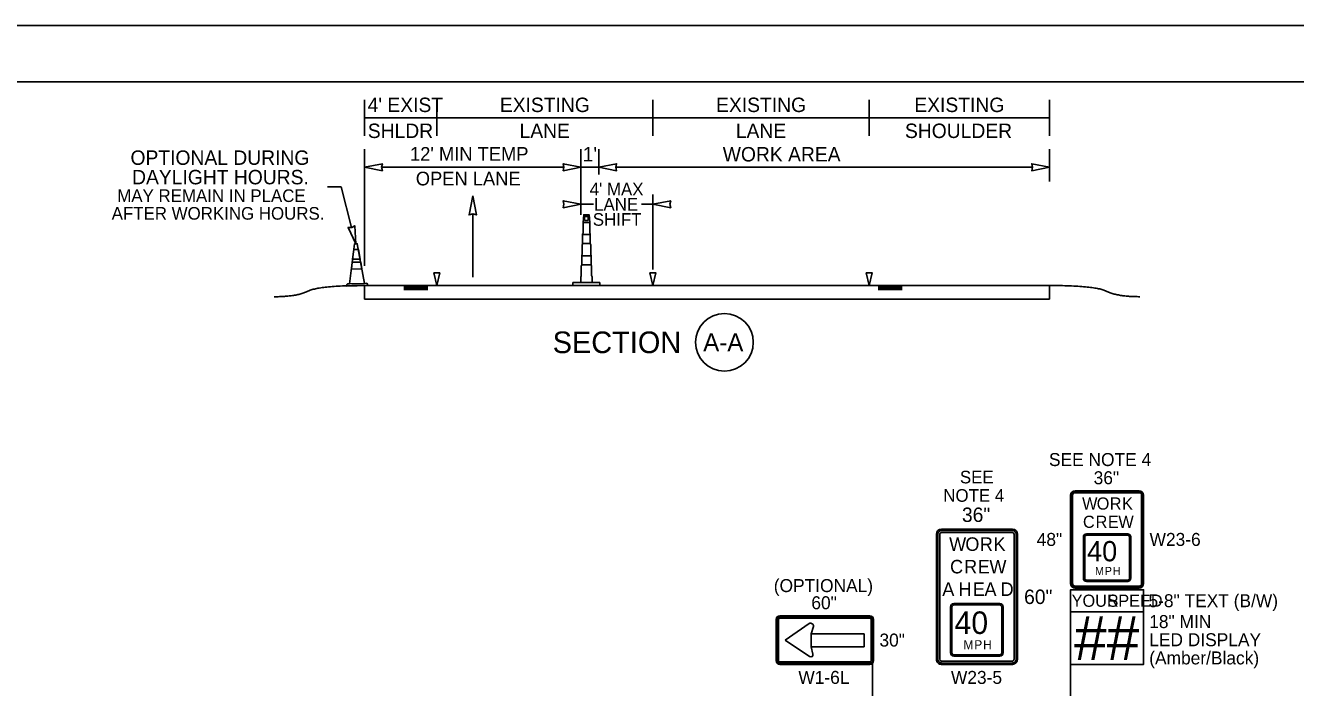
# Model space of a CAD drawing. Extents: x 99999 to 100116, y 99995 to 100013.
# Drawn here: x 100024.18 to 100031.22, y 100007.02 to 100010.69 of the extents above; entities that cross this region are included whole.
import ezdxf

# ---------------------------------------------------------------- set-up
doc = ezdxf.new("R2010")
doc.units = 0
for name, color, linetype in [('SH_GI_PlotLimits', 7, 'Continuous'), ('SH_GI_SheetBorder', 7, 'Continuous'), ('SH_TI_WZSectionCut', 7, 'Continuous'), ('TR_SN_ConstructionSigns', 7, 'Continuous'), ('TR_WZ_ArrowLeftStrRightTurn', 7, 'Continuous'), ('TR_WZ_TallChanDeviceElev', 7, 'Continuous'), ('TR_WZ_TrafficConeElev', 7, 'Continuous'), ('TR_WZ_WorkZoneDetails', 7, 'Continuous'), ('TR_WZ_WorkZoneTextCurrent', 7, 'Continuous')]:
    doc.layers.add(name, color=color, linetype=linetype)

msp = doc.modelspace()

# ---------------------------------------------------------------- linework, layer by layer
at = {"layer": 'SH_GI_PlotLimits'}
msp.add_lwpolyline([(100019.0625, 99999.6875), (100036.0625, 99999.6875), (100036.0625, 100010.6875), (100019.0625, 100010.6875)], close=True, dxfattribs=at)
at = {"layer": 'SH_GI_SheetBorder'}
msp.add_line((100020, 100010.375), (100035.75, 100010.375), dxfattribs=at)
at = {"layer": 'SH_TI_WZSectionCut'}
for p, q in [((100026.0578, 100010.075), (100026.0578, 100010.275)), ((100026.4578, 100010.075), (100026.4578, 100010.275)), ((100027.6578, 100010.075), (100027.6578, 100010.275)), ((100028.8578, 100010.075), (100028.8578, 100010.275)), ((100029.8578, 100010.075), (100029.8578, 100010.275)), ((100026.0578, 100010.175), (100026.4578, 100010.175)), ((100026.4578, 100010.175), (100027.6578, 100010.175)), ((100027.6578, 100010.175), (100028.8578, 100010.175)), ((100028.8578, 100010.175), (100029.8578, 100010.175)), ((100026.0578, 100009.3547), (100026.0578, 100010.001)), ((100027.2578, 100009.6378), (100027.2578, 100010.001)), ((100027.3578, 100009.861), (100027.3578, 100010.001)), ((100029.8578, 100009.821), (100029.8578, 100010.001)), ((100026.1515, 100009.901), (100027.164, 100009.901)), ((100027.2578, 100009.901), (100027.3578, 100009.901)), ((100027.4515, 100009.901), (100029.764, 100009.901)), ((100027.6578, 100009.3347), (100027.6578, 100009.75)), ((100027.2578, 100009.6955), (100027.3274, 100009.6955)), ((100027.5945, 100009.6955), (100027.6578, 100009.6955)), ((100026.0578, 100009.2449), (100026.0578, 100009.1699)), ((100029.8578, 100009.2449), (100026.0578, 100009.2449)), ((100026.2748, 100009.2397), (100026.4078, 100009.2397)), ((100026.2748, 100009.2341), (100026.4078, 100009.2341)), ((100026.2748, 100009.2284), (100026.4078, 100009.2284)), ((100026.2748, 100009.2232), (100026.4078, 100009.2232)), ((100029.0408, 100009.2393), (100028.9078, 100009.2393)), ((100029.0408, 100009.2337), (100028.9078, 100009.2337)), ((100029.0408, 100009.228), (100028.9078, 100009.228)), ((100029.0408, 100009.2228), (100028.9078, 100009.2228)), ((100029.8578, 100009.2449), (100029.8578, 100009.1699)), ((100029.8578, 100009.1699), (100026.0578, 100009.1699))]:
    msp.add_line(p, q, dxfattribs=at)
for points in [[(100026.0578, 100009.901), (100026.156, 100009.8817), (100026.1515, 100009.901), (100026.156, 100009.9203)], [(100027.2578, 100009.901), (100027.1595, 100009.8817), (100027.164, 100009.901), (100027.1595, 100009.9203)], [(100027.3578, 100009.901), (100027.456, 100009.8817), (100027.4515, 100009.901), (100027.456, 100009.9203)], [(100029.8578, 100009.901), (100029.7595, 100009.8817), (100029.764, 100009.901), (100029.7595, 100009.9203)], [(100027.2578, 100009.6955), (100027.1595, 100009.6762), (100027.164, 100009.6955), (100027.1595, 100009.7148)], [(100027.6578, 100009.6955), (100027.756, 100009.6762), (100027.7515, 100009.6955), (100027.756, 100009.7148)], [(100026.4411, 100009.3147), (100026.4744, 100009.3147), (100026.4578, 100009.2449)], [(100027.6411, 100009.3147), (100027.6744, 100009.3147), (100027.6578, 100009.2449)], [(100028.8411, 100009.3147), (100028.8744, 100009.3147), (100028.8578, 100009.2449)]]:
    msp.add_lwpolyline(points, close=True, dxfattribs=at)
msp.add_circle((100028.0543, 100008.93), 0.16, dxfattribs=at)
for points in [[(100026.0578, 100009.2449), (100025.8066, 100009.2449), (100025.6811, 100009.1828), (100025.5556, 100009.1828)], [(100029.8578, 100009.2449), (100030.1089, 100009.2451), (100030.2344, 100009.183), (100030.3599, 100009.1831)]]:
    msp.add_open_spline(points, degree=2, dxfattribs=at)
at = {"layer": 'TR_SN_ConstructionSigns'}
for p, q in [((100029.9753, 100008.0817), (100029.9753, 100007.5923)), ((100029.9795, 100008.0817), (100029.9795, 100007.5923)), ((100029.9865, 100007.5923), (100029.9865, 100008.0817)), ((100030.355, 100008.107), (100030.0006, 100008.107)), ((100030.355, 100008.1028), (100030.0006, 100008.1028)), ((100030.0006, 100008.0958), (100030.355, 100008.0958)), ((100030.369, 100008.0817), (100030.369, 100007.5923)), ((100030.3761, 100007.5923), (100030.3761, 100008.0817)), ((100030.3803, 100007.5923), (100030.3803, 100008.0817)), ((100029.6521, 100007.8937), (100029.2584, 100007.8937)), ((100029.6521, 100007.8859), (100029.2584, 100007.8859)), ((100029.2584, 100007.875), (100029.6521, 100007.875)), ((100030.2924, 100007.8672), (100030.0632, 100007.8672)), ((100029.2302, 100007.8656), (100029.2302, 100007.1719)), ((100029.2381, 100007.8656), (100029.2381, 100007.1719)), ((100029.249, 100007.1719), (100029.249, 100007.8656)), ((100029.6615, 100007.8656), (100029.6615, 100007.1719)), ((100029.6724, 100007.1719), (100029.6724, 100007.8656)), ((100029.6802, 100007.1719), (100029.6802, 100007.8656)), ((100030.0463, 100007.8504), (100030.0463, 100007.6212)), ((100030.0533, 100007.6212), (100030.0533, 100007.8504)), ((100030.0632, 100007.8602), (100030.2924, 100007.8602)), ((100030.3022, 100007.8504), (100030.3022, 100007.6212)), ((100030.3093, 100007.6212), (100030.3093, 100007.8504)), ((100030.2924, 100007.6113), (100030.0632, 100007.6113)), ((100030.0632, 100007.6043), (100030.2924, 100007.6043)), ((100030.355, 100007.5783), (100030.0006, 100007.5783)), ((100030.0006, 100007.5712), (100030.355, 100007.5712)), ((100030.0006, 100007.567), (100030.355, 100007.567)), ((100029.3091, 100007.4625), (100029.3091, 100007.2078)), ((100029.317, 100007.2078), (100029.317, 100007.4625)), ((100029.5826, 100007.4812), (100029.3279, 100007.4812)), ((100029.3279, 100007.4734), (100029.5826, 100007.4734)), ((100029.5935, 100007.4625), (100029.5935, 100007.2078)), ((100029.6013, 100007.2078), (100029.6013, 100007.4625)), ((100028.3412, 100007.3935), (100028.3412, 100007.164)), ((100028.3469, 100007.3935), (100028.3469, 100007.164)), ((100028.3547, 100007.164), (100028.3547, 100007.3935)), ((100028.861, 100007.4137), (100028.3615, 100007.4137)), ((100028.861, 100007.4081), (100028.3615, 100007.4081)), ((100028.3615, 100007.4002), (100028.861, 100007.4002)), ((100028.8677, 100007.3935), (100028.8677, 100007.164)), ((100028.8756, 100007.164), (100028.8756, 100007.3935)), ((100028.8812, 100007.164), (100028.8812, 100007.3935)), ((100029.9753, 100007.4362), (100030.3803, 100007.4362)), ((100030.3803, 100007.4362), (100029.9753, 100007.4362)), ((100028.525, 100007.3699), (100028.3919, 100007.278)), ((100028.536, 100007.314), (100028.5476, 100007.3546)), ((100028.536, 100007.3122), (100028.536, 100007.314)), ((100028.8306, 100007.314), (100028.536, 100007.314)), ((100028.536, 100007.314), (100028.536, 100007.3122)), ((100028.536, 100007.2438), (100028.536, 100007.3122)), ((100028.536, 100007.3122), (100028.536, 100007.2438)), ((100028.8306, 100007.242), (100028.8306, 100007.314)), ((100028.3919, 100007.278), (100028.5269, 100007.1878)), ((100028.536, 100007.242), (100028.536, 100007.2438)), ((100028.536, 100007.2438), (100028.536, 100007.242)), ((100028.5455, 100007.2001), (100028.536, 100007.242)), ((100028.536, 100007.242), (100028.8306, 100007.242)), ((100029.6521, 100007.1625), (100029.2584, 100007.1625)), ((100029.5826, 100007.1969), (100029.3279, 100007.1969)), ((100029.3279, 100007.189), (100029.5826, 100007.189)), ((100028.861, 100007.1572), (100028.3615, 100007.1572)), ((100028.3615, 100007.1494), (100028.861, 100007.1494)), ((100028.3615, 100007.1437), (100028.861, 100007.1437)), ((100029.2584, 100007.1515), (100029.6521, 100007.1515)), ((100029.2584, 100007.1437), (100029.6521, 100007.1437))]:
    msp.add_line(p, q, dxfattribs=at)
for points in [[(100030.3803, 100007.4362), (100030.3803, 100007.558), (100029.9753, 100007.558), (100029.9753, 100007.4362)], [(100029.9753, 100007.4362), (100029.9753, 100007.1437), (100030.3803, 100007.1437), (100030.3803, 100007.4362)]]:
    msp.add_lwpolyline(points, dxfattribs=at)
for points in [[(100029.9753, 100007.558), (100030.3803, 100007.558), (100030.3803, 100007.4362), (100029.9753, 100007.4362)], [(100029.9753, 100007.4362), (100030.3803, 100007.4362), (100030.3803, 100007.1437), (100029.9753, 100007.1437)]]:
    msp.add_lwpolyline(points, close=True, dxfattribs=at)
for centre, radius, start, end in [((100030.0006, 100008.0817), 0.0253, 90, 180), ((100030.0006, 100008.0817), 0.0211, 90, 180.00001), ((100030.0006, 100008.0817), 0.0141, 90, 180.00001), ((100030.355, 100008.0817), 0.0253, 0, 90), ((100030.355, 100008.0817), 0.0211, 0, 90), ((100030.355, 100008.0817), 0.0141, 0, 90), ((100029.2584, 100007.8656), 0.0281, 90, 180), ((100029.2584, 100007.8656), 0.0203, 90, 180.00001), ((100029.2584, 100007.8656), 0.00937, 90, 180.00001), ((100029.6521, 100007.8656), 0.0281, 0, 90), ((100029.6521, 100007.8656), 0.0203, 0, 90), ((100029.6521, 100007.8656), 0.00937, 0, 90), ((100030.0632, 100007.8504), 0.0169, 90, 180), ((100030.2924, 100007.8504), 0.0169, 0, 90), ((100030.0632, 100007.8504), 0.00984, 90, 180.00001), ((100030.2924, 100007.8504), 0.00984, 0, 90), ((100030.0006, 100007.5923), 0.0253, 180, 270.00001), ((100030.0006, 100007.5923), 0.0211, 180.00001, 270), ((100030.0006, 100007.5923), 0.0141, 180.00001, 270), ((100030.0632, 100007.6212), 0.0169, 180, 270.00001), ((100030.0632, 100007.6212), 0.00984, 180.00001, 270), ((100030.2924, 100007.6212), 0.0169, 270, 0.00001), ((100030.2924, 100007.6212), 0.00984, 270, 0.00001), ((100030.355, 100007.5923), 0.0211, 270, 0.00001), ((100030.355, 100007.5923), 0.0141, 270, 0.00001), ((100030.355, 100007.5923), 0.0253, 270.00001, 0.00001), ((100029.3279, 100007.4625), 0.0187, 90, 180.00001), ((100029.3279, 100007.4625), 0.0109, 90, 180.00001), ((100029.5826, 100007.4625), 0.0187, 0, 90), ((100029.5826, 100007.4625), 0.0109, 0, 90), ((100028.3615, 100007.3935), 0.0202, 90, 180), ((100028.3615, 100007.3935), 0.0146, 90, 180), ((100028.3615, 100007.3935), 0.00675, 90, 180), ((100028.861, 100007.3935), 0.0202, 360, 90), ((100028.861, 100007.3935), 0.0146, 360, 90), ((100028.861, 100007.3935), 0.00675, 360, 90), ((100028.3615, 100007.164), 0.0202, 180, 270), ((100028.3615, 100007.164), 0.0146, 180, 270), ((100028.3615, 100007.164), 0.00675, 180, 270), ((100028.861, 100007.164), 0.0202, 270, 0), ((100028.861, 100007.164), 0.0146, 270, 0), ((100028.861, 100007.164), 0.00675, 270, 0), ((100029.2584, 100007.1719), 0.0281, 180, 270.00001), ((100029.2584, 100007.1719), 0.0203, 180.00001, 270), ((100029.2584, 100007.1719), 0.00937, 180.00001, 270), ((100029.3279, 100007.2078), 0.0187, 180, 270.00001), ((100029.3279, 100007.2078), 0.0109, 180.00001, 270), ((100029.5826, 100007.2078), 0.0187, 270.00001, 0.00001), ((100029.5826, 100007.2078), 0.0109, 270, 0.00001), ((100029.6521, 100007.1719), 0.0203, 270, 0.00001), ((100029.6521, 100007.1719), 0.00937, 270, 0.00001), ((100029.6521, 100007.1719), 0.0281, 270.00001, 0.00001)]:
    msp.add_arc(centre, radius, start, end, dxfattribs=at)
for centre, major_axis, ratio, start_param, end_param in [((100028.5334, 100007.3585), (0.0142, -0.0039), 0.918316, 0, 2.426314), ((100028.5334, 100007.1976), (0.0109, -0.0073), 0.895682, 4.712389, 7.138703)]:
    msp.add_ellipse(centre, major_axis=major_axis, ratio=ratio, start_param=start_param, end_param=end_param, dxfattribs=at)
at = {"layer": 'TR_WZ_ArrowLeftStrRightTurn'}
msp.add_line((100026.6578, 100009.6418), (100026.6578, 100009.292), dxfattribs=at)
msp.add_lwpolyline([(100026.6578, 100009.742), (100026.6372, 100009.6369), (100026.6578, 100009.6418), (100026.6784, 100009.6369)], close=True, dxfattribs=at)
at = {"layer": 'TR_WZ_TallChanDeviceElev'}
for p, q in [((100027.307, 100009.595), (100027.2702, 100009.595)), ((100027.2702, 100009.595), (100027.307, 100009.595)), ((100027.2702, 100009.595), (100027.307, 100009.595)), ((100027.298, 100009.6275), (100027.2785, 100009.6275)), ((100027.2785, 100009.6052), (100027.298, 100009.6052)), ((100027.2675, 100009.5278), (100027.3097, 100009.5278)), ((100027.2675, 100009.4784), (100027.2675, 100009.5278)), ((100027.3097, 100009.5278), (100027.3097, 100009.4784)), ((100027.3097, 100009.4784), (100027.2675, 100009.4784)), ((100027.2627, 100009.3599), (100027.2627, 100009.4093)), ((100027.2627, 100009.4093), (100027.3146, 100009.4093)), ((100027.3146, 100009.3599), (100027.2627, 100009.3599)), ((100027.3146, 100009.4093), (100027.3146, 100009.3599)), ((100027.2136, 100009.245), (100027.2136, 100009.2615)), ((100027.3636, 100009.245), (100027.2136, 100009.245)), ((100027.3636, 100009.2615), (100027.3636, 100009.245))]:
    msp.add_line(p, q, dxfattribs=at)
for points in [[(100027.307, 100009.595), (100027.3036, 100009.6378), (100027.2734, 100009.6378), (100027.2702, 100009.595)], [(100027.3097, 100009.5278), (100027.2675, 100009.5278), (100027.2675, 100009.4784), (100027.3097, 100009.4784)], [(100027.3146, 100009.4093), (100027.2627, 100009.4093), (100027.2627, 100009.3599), (100027.3146, 100009.3599)]]:
    msp.add_lwpolyline(points, close=True, dxfattribs=at)
for points in [[(100027.27, 100009.5348), (100027.27, 100009.5909)], [(100027.27, 100009.5348), (100027.27, 100009.5909)], [(100027.3072, 100009.5909), (100027.3072, 100009.5348)], [(100027.3072, 100009.5909), (100027.3072, 100009.5348)], [(100027.2675, 100009.4755), (100027.2675, 100009.5308)], [(100027.2675, 100009.4755), (100027.2675, 100009.5308)], [(100027.3097, 100009.5308), (100027.3097, 100009.4755)], [(100027.3097, 100009.5308), (100027.3097, 100009.4755)], [(100027.2651, 100009.4162), (100027.2651, 100009.4715)], [(100027.2651, 100009.4162), (100027.2651, 100009.4715)], [(100027.3121, 100009.4715), (100027.3121, 100009.4162)], [(100027.3121, 100009.4715), (100027.3121, 100009.4162)], [(100027.2602, 100009.298), (100027.2602, 100009.3531)], [(100027.2602, 100009.298), (100027.2602, 100009.3531)], [(100027.2627, 100009.3571), (100027.2627, 100009.4122)], [(100027.2627, 100009.3571), (100027.2627, 100009.4122)], [(100027.3146, 100009.4122), (100027.3146, 100009.3571)], [(100027.3146, 100009.4122), (100027.3146, 100009.3571)], [(100027.317, 100009.3531), (100027.317, 100009.298)], [(100027.317, 100009.3531), (100027.317, 100009.298)], [(100027.3195, 100009.2615), (100027.2578, 100009.2615), (100027.2578, 100009.294)], [(100027.3195, 100009.2615), (100027.2578, 100009.2615), (100027.2578, 100009.294)], [(100027.3195, 100009.294), (100027.3195, 100009.2615)], [(100027.3195, 100009.294), (100027.3195, 100009.2615)], [(100027.2136, 100009.2615), (100027.2578, 100009.2615), (100027.3195, 100009.2615), (100027.3636, 100009.2615)]]:
    msp.add_lwpolyline(points, dxfattribs=at)
for centre, major_axis, ratio, start_param, end_param in [((100027.2703, 100009.5899), (0, 0.00515), 0.059356, 0.177149, 1.393647), ((100027.2703, 100009.5899), (0, 0.00515), 0.059356, 0.177149, 1.393647), ((100027.2785, 100009.6164), (0, 0.0111), 0.07945, 0, 3.141593), ((100027.298, 100009.6164), (0, 0.0111), 0.07945, 3.141593, 6.283185), ((100027.3069, 100009.5899), (0, 0.00515), 0.059356, 4.889538, 6.106036), ((100027.3069, 100009.5899), (0, 0.00515), 0.059356, 4.889538, 6.106036), ((100027.2721, 100009.5274), (0, 0.00814), 0.609371, 0.4288, 1.141997), ((100027.2721, 100009.5274), (0, 0.00814), 0.609371, 0.4288, 1.141997), ((100027.3052, 100009.5274), (0, 0.00814), 0.609371, 5.141189, 5.854386), ((100027.3052, 100009.5274), (0, 0.00814), 0.609371, 5.141189, 5.854386), ((100027.2696, 100009.4681), (0, 0.00814), 0.609371, 0.4288, 1.141997), ((100027.2696, 100009.4681), (0, 0.00814), 0.609371, 0.4288, 1.141997), ((100027.3076, 100009.4681), (0, 0.00814), 0.609371, 5.141189, 5.854386), ((100027.3076, 100009.4681), (0, 0.00814), 0.609371, 5.141189, 5.854386), ((100027.2647, 100009.3497), (0, 0.00814), 0.609371, 0.4288, 1.141997), ((100027.2647, 100009.3497), (0, 0.00814), 0.609371, 0.4288, 1.141997), ((100027.2672, 100009.4088), (0, 0.00814), 0.609371, 0.4288, 1.141997), ((100027.2672, 100009.4088), (0, 0.00814), 0.609371, 0.4288, 1.141997), ((100027.3101, 100009.4088), (0, 0.00814), 0.609371, 5.141189, 5.854386), ((100027.3101, 100009.4088), (0, 0.00814), 0.609371, 5.141189, 5.854386), ((100027.3125, 100009.3497), (0, 0.00814), 0.609371, 5.141189, 5.854386), ((100027.3125, 100009.3497), (0, 0.00814), 0.609371, 5.141189, 5.854386), ((100027.2623, 100009.2906), (0, 0.00814), 0.609371, 0.4288, 1.141997), ((100027.2623, 100009.2906), (0, 0.00814), 0.609371, 0.4288, 1.141997), ((100027.315, 100009.2906), (0, 0.00814), 0.609371, 5.141189, 5.854386), ((100027.315, 100009.2906), (0, 0.00814), 0.609371, 5.141189, 5.854386)]:
    msp.add_ellipse(centre, major_axis=major_axis, ratio=ratio, start_param=start_param, end_param=end_param, dxfattribs=at)
at = {"layer": 'TR_WZ_TrafficConeElev'}
for p, q in [((100025.9909, 100009.3905), (100025.9976, 100009.4449)), ((100025.9976, 100009.4449), (100026.0228, 100009.4456)), ((100026.0228, 100009.4456), (100026.0327, 100009.3917)), ((100025.9842, 100009.3361), (100025.9888, 100009.3738)), ((100025.9888, 100009.3738), (100026.0357, 100009.3751)), ((100026.0327, 100009.3917), (100025.9909, 100009.3905)), ((100026.0357, 100009.3751), (100026.0426, 100009.3378)), ((100026.0426, 100009.3378), (100025.9842, 100009.3361)), ((100025.9581, 100009.2499), (100025.9621, 100009.2542)), ((100025.9583, 100009.2416), (100025.9581, 100009.2499)), ((100026.0739, 100009.2449), (100025.9583, 100009.2416)), ((100026.0574, 100009.257), (100026.0694, 100009.2573)), ((100026.0694, 100009.2573), (100026.0737, 100009.2533)), ((100026.0737, 100009.2533), (100026.0739, 100009.2449))]:
    msp.add_line(p, q, dxfattribs=at)
msp.add_lwpolyline([(100026.0574, 100009.257), (100025.9741, 100009.2545), (100026.0015, 100009.4763), (100026.0171, 100009.4767)], close=True, dxfattribs=at)
msp.add_lwpolyline([(100026.0574, 100009.257), (100025.9741, 100009.2545), (100026.0015, 100009.4763), (100026.0171, 100009.4767)], close=True, dxfattribs=at)
msp.add_lwpolyline([(100025.9621, 100009.2542), (100025.9741, 100009.2545), (100026.0574, 100009.257)], dxfattribs=at)
at = {"layer": 'TR_WZ_WorkZoneDetails'}
for p, q in [((100025.8511, 100009.7922), (100025.9274, 100009.7922)), ((100025.9857, 100009.5672), (100025.9274, 100009.7922)), ((100028.8753, 100006.1157), (100028.8753, 100007.1497)), ((100029.9753, 100006.1558), (100029.9753, 100007.1437))]:
    msp.add_line(p, q, dxfattribs=at)
msp.add_lwpolyline([(100026.0093, 100009.4765), (100025.966, 100009.5668), (100025.9858, 100009.5672), (100026.0033, 100009.5765)], close=True, dxfattribs=at)

# ---------------------------------------------------------------- texts
at = {"layer": 'SH_TI_WZSectionCut'}
for s, height, p in [("4' EXIST", 0.08, (100026.0744, 100010.207)), ('EXISTING', 0.08, (100026.808, 100010.207)), ('EXISTING', 0.08, (100028.008, 100010.207)), ('EXISTING', 0.08, (100029.108, 100010.207)), ('SHLDR', 0.08, (100026.0753, 100010.063)), ('LANE', 0.08, (100026.9174, 100010.063)), ('LANE', 0.08, (100028.1174, 100010.063)), ('SHOULDER', 0.08, (100029.056, 100010.063)), ('SECTION', 0.12, (100027.1012, 100008.87)), ('A-A', 0.1, (100027.9364, 100008.88))]:
    msp.add_text(s, height=height, rotation=360, dxfattribs=at).set_placement(p)
for s, height, p in [("12' MIN TEMP", 0.076, (100026.3095, 100009.937)), ("1'", 0.08, (100027.2677, 100009.933)), ('WORK AREA', 0.08, (100028.0449, 100009.933)), ('OPEN LANE', 0.076, (100026.3417, 100009.8002)), ("4' MAX", 0.07, (100027.3064, 100009.7445)), ('LANE', 0.07, (100027.331, 100009.6605)), ('SHIFT', 0.07, (100027.3237, 100009.5765))]:
    msp.add_text(s, height=height, dxfattribs=at).set_placement(p)
at = {"layer": 'TR_SN_ConstructionSigns'}
for s, height, p in [('SEE NOTE 4', 0.072, (100029.8551, 100008.2438)), ('SEE', 0.07, (100029.3611, 100008.1477)), ('36"', 0.072, (100030.103, 100008.143)), ('NOTE 4', 0.07, (100029.2687, 100008.0457)), ('36"', 0.08, (100029.3722, 100007.9337)), ('W23-6', 0.072, (100030.4135, 100007.801)), ('(OPTIONAL)', 0.072, (100028.3281, 100007.5448)), ('60"', 0.072, (100028.5365, 100007.4497)), ('60"', 0.08, (100029.7172, 100007.4787)), ('YOUR', 0.0675, (100029.981, 100007.4633)), ('SPEED', 0.0675, (100030.1797, 100007.4633)), ('30"', 0.072, (100028.9145, 100007.2427)), ('W1-6L', 0.072, (100028.4645, 100007.0357)), ('W23-5', 0.072, (100029.3113, 100007.0357))]:
    msp.add_text(s, height=height, rotation=360, dxfattribs=at).set_placement(p)
for s, height, p in [('W', 0.0675, (100030.0391, 100008.0022)), ('O', 0.0675, (100030.1201, 100008.0022)), ('R', 0.0675, (100030.1923, 100008.0022)), ('K', 0.0675, (100030.2605, 100008.0022)), ('C', 0.0675, (100030.0438, 100007.901)), ('R', 0.0675, (100030.114, 100007.901)), ('E', 0.0675, (100030.1822, 100007.901)), ('W', 0.0675, (100030.2402, 100007.901)), ('48"', 0.072, (100029.7871, 100007.801)), ('W', 0.075, (100029.3011, 100007.7734)), ('O', 0.075, (100029.3911, 100007.7734)), ('R', 0.075, (100029.4714, 100007.7734)), ('K', 0.075, (100029.5471, 100007.7734)), ('40', 0.1125, (100030.0665, 100007.7154)), ('C', 0.075, (100029.3064, 100007.6484)), ('R', 0.075, (100029.3844, 100007.6484)), ('E', 0.075, (100029.4601, 100007.6484)), ('W', 0.075, (100029.5246, 100007.6484)), ('M', 0.045, (100030.1105, 100007.6394)), ('P', 0.045, (100030.1645, 100007.6394)), ('H', 0.045, (100030.2086, 100007.6394)), ('A', 0.075, (100029.2632, 100007.5234)), ('H', 0.075, (100029.3525, 100007.5234)), ('E', 0.075, (100029.4327, 100007.5234)), ('A', 0.075, (100029.4972, 100007.5234)), ('D', 0.075, (100029.5865, 100007.5234)), ('5-8" TEXT (B/W)', 0.072, (100030.4074, 100007.4611)), ('40', 0.125, (100029.3315, 100007.3125)), ('##', 0.243, (100029.9952, 100007.1684)), ('18" MIN', 0.072, (100030.4115, 100007.3453)), ('LED DISPLAY', 0.072, (100030.4115, 100007.2445)), ('M', 0.05, (100029.3805, 100007.2281)), ('P', 0.05, (100029.4405, 100007.2281)), ('H', 0.05, (100029.4895, 100007.2281)), ('(Amber/Black)', 0.072, (100030.4115, 100007.1437))]:
    msp.add_text(s, height=height, dxfattribs=at).set_placement(p)
at = {"layer": 'TR_WZ_WorkZoneTextCurrent'}
for s, height, p in [('OPTIONAL DURING', 0.08, (100024.7584, 100009.9142)), ('DAYLIGHT HOURS.', 0.08, (100024.7674, 100009.8062)), ('MAY REMAIN IN PLACE', 0.07, (100024.685, 100009.7082)), ('AFTER WORKING HOURS.', 0.07, (100024.6541, 100009.6102))]:
    msp.add_text(s, height=height, dxfattribs=at).set_placement(p)

doc.saveas('drawing.dxf')
